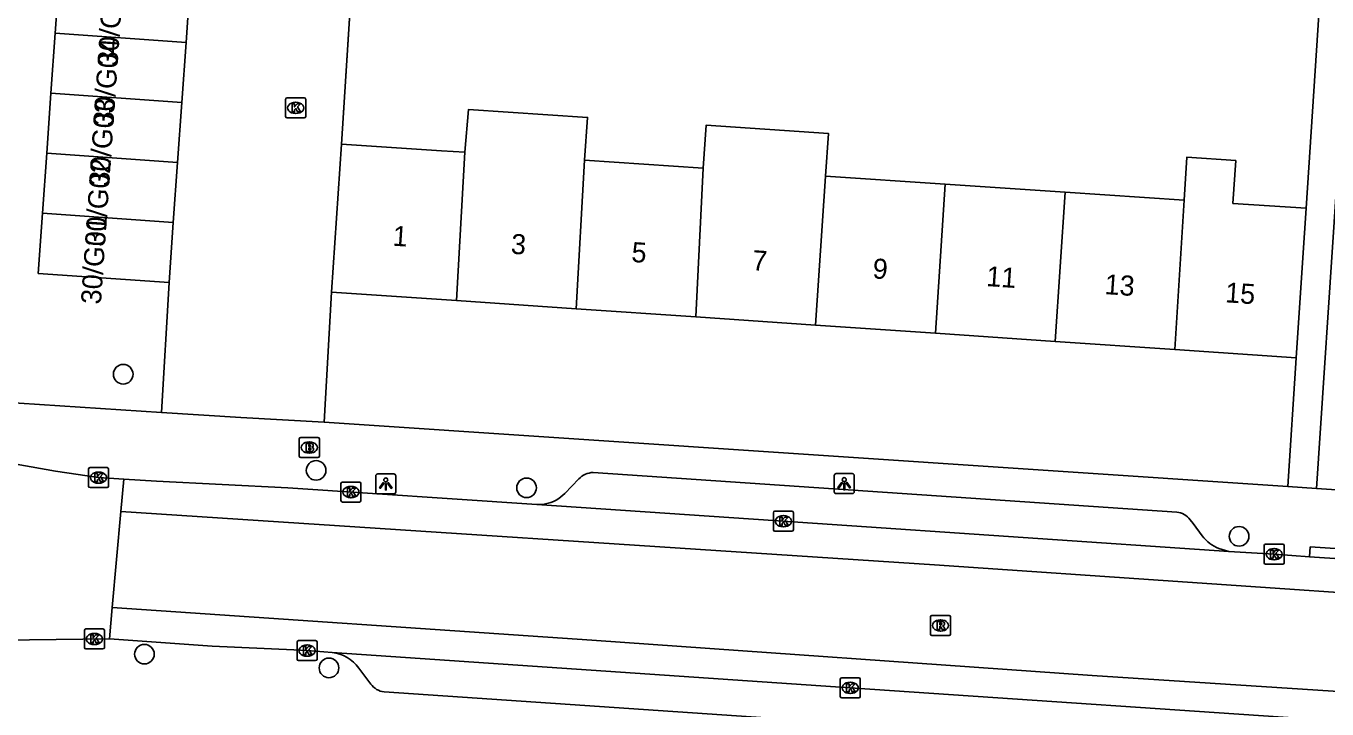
# Model space of a CAD drawing. Extents: x 161848 to 162726, y 385382 to 386521.
# Drawn here: x 162036.5 to 162101.4, y 385740.7 to 385774.8 of the extents above; entities that cross this region are included whole.
import ezdxf

# ---------------------------------------------------------------- set-up
doc = ezdxf.new("R2010")
doc.units = 0
for name, color, linetype in [('IMGEO_Boom', 7, 'Continuous'), ('IMGEO_Brandkraan', 7, 'Continuous'), ('IMGEO_Kolk', 7, 'Continuous'), ('IMGEO_Lichtpunt', 7, 'Continuous'), ('IMGEO_Muur', 7, 'Continuous'), ('IMGEO_Pand', 7, 'Continuous'), ('IMGEO_Pand_nummerreeks', 7, 'Continuous'), ('IMGEO_Rijbaan_lokaal_gesloten', 7, 'Continuous'), ('IMGEO_Rijbaan_lokaal_open', 7, 'Continuous'), ('IMGEO_Rioolput', 7, 'Continuous'), ('IMGEO_Voetpad_open', 7, 'Continuous')]:
    doc.layers.add(name, color=color, linetype=linetype)

msp = doc.modelspace()

# ---------------------------------------------------------------- linework, layer by layer
at = {"layer": 'IMGEO_Boom'}
for centre in [(162041.355, 385757.451), (162050.975, 385752.654), (162061.466, 385751.784), (162096.994, 385749.363), (162042.412, 385743.486), (162051.615, 385742.801)]:
    msp.add_circle(centre, 0.489, dxfattribs=at)
at = {"layer": 'IMGEO_Brandkraan'}
for p, q in [((162050.134, 385753.369), (162050.134, 385754.221)), ((162050.209, 385754.295), (162051.061, 385754.295)), ((162051.135, 385754.221), (162051.135, 385753.369)), ((162050.645, 385753.515), (162050.62, 385753.515)), ((162050.622, 385754.075), (162050.647, 385754.075)), ((162051.061, 385753.295), (162050.209, 385753.295))]:
    msp.add_line(p, q, dxfattribs=at)
for points in [[(162050.134, 385753.369), (162050.134, 385754.221)], [(162050.209, 385754.295), (162051.061, 385754.295)], [(162051.135, 385754.221), (162051.135, 385753.369)], [(162050.482, 385753.995), (162050.482, 385753.595), (162050.695, 385753.595)], [(162050.713, 385753.995), (162050.482, 385753.995)], [(162050.661, 385753.914), (162050.607, 385753.914), (162050.607, 385753.838)], [(162050.607, 385753.838), (162050.66, 385753.838)], [(162050.669, 385753.762), (162050.607, 385753.762), (162050.607, 385753.681)], [(162050.607, 385753.681), (162050.669, 385753.681)], [(162051.061, 385753.295), (162050.209, 385753.295)]]:
    msp.add_lwpolyline(points, dxfattribs=at)
for centre, radius, start, end in [((162050.211, 385754.219), 0.0765, 91.55205, 178.44795), ((162050.211, 385754.219), 0.0765, 91.55205, 178.44795), ((162051.059, 385754.219), 0.0765, 1.55205, 88.44795), ((162051.059, 385754.219), 0.0765, 1.55205, 88.44795), ((162050.662, 385753.876), 0.0379, 267.82845, 90.93552), ((162050.67, 385753.721), 0.0404, 269.87594, 90.50774), ((162050.701, 385753.846), 0.251, 268.66757, 293.53466), ((162050.717, 385753.85), 0.145, 59.4692, 91.53667), ((162050.742, 385753.897), 0.0922, 285.51372, 58.15012), ((162050.747, 385753.705), 0.105, 301.31148, 78.98903), ((162050.211, 385753.371), 0.0765, 181.55205, 268.44795), ((162050.211, 385753.371), 0.0765, 181.55205, 268.44795), ((162051.059, 385753.371), 0.0765, 271.55205, 358.44795), ((162051.059, 385753.371), 0.0765, 271.55205, 358.44795)]:
    msp.add_arc(centre, radius, start, end, dxfattribs=at)
for centre, major_axis, ratio, start_param, end_param in [((162050.621, 385753.795), (-0.387, 0.002), 0.722429, 4.712389, 7.853982), ((162050.646, 385753.795), (-0.39, 0.002), 0.717154, 1.570796, 4.712389)]:
    msp.add_ellipse(centre, major_axis=major_axis, ratio=ratio, start_param=start_param, end_param=end_param, dxfattribs=at)
at = {"layer": 'IMGEO_Kolk'}
for p, q in [((162049.455, 385770.312), (162049.455, 385771.164)), ((162049.53, 385771.238), (162050.382, 385771.238)), ((162049.943, 385771.018), (162049.968, 385771.018)), ((162050.456, 385771.164), (162050.456, 385770.312)), ((162049.966, 385770.458), (162049.941, 385770.458)), ((162050.382, 385770.238), (162049.53, 385770.238)), ((162039.625, 385751.867), (162039.625, 385752.719)), ((162039.7, 385752.793), (162040.552, 385752.793)), ((162040.113, 385752.573), (162040.138, 385752.573)), ((162040.626, 385752.719), (162040.626, 385751.867)), ((162040.552, 385751.793), (162039.7, 385751.793)), ((162040.136, 385752.013), (162040.111, 385752.013)), ((162052.21, 385751.147), (162052.21, 385751.999)), ((162052.285, 385752.073), (162053.137, 385752.073)), ((162052.698, 385751.853), (162052.723, 385751.853)), ((162053.211, 385751.999), (162053.211, 385751.147)), ((162053.137, 385751.073), (162052.285, 385751.073)), ((162052.721, 385751.293), (162052.696, 385751.293)), ((162073.772, 385749.691), (162073.772, 385750.543)), ((162073.847, 385750.617), (162074.699, 385750.617)), ((162074.26, 385750.397), (162074.285, 385750.397)), ((162074.773, 385750.543), (162074.773, 385749.691)), ((162074.699, 385749.617), (162073.847, 385749.617)), ((162074.283, 385749.837), (162074.258, 385749.837)), ((162098.316, 385748.974), (162099.168, 385748.974)), ((162098.241, 385748.048), (162098.241, 385748.9)), ((162098.729, 385748.754), (162098.754, 385748.754)), ((162099.242, 385748.9), (162099.242, 385748.048)), ((162099.168, 385747.974), (162098.316, 385747.974)), ((162098.752, 385748.194), (162098.727, 385748.194)), ((162039.419, 385743.818), (162039.419, 385744.67)), ((162039.494, 385744.744), (162040.346, 385744.744)), ((162039.907, 385744.524), (162039.932, 385744.524)), ((162040.42, 385744.67), (162040.42, 385743.818)), ((162040.346, 385743.744), (162039.494, 385743.744)), ((162039.93, 385743.964), (162039.905, 385743.964)), ((162050.023, 385743.237), (162050.023, 385744.089)), ((162050.098, 385744.163), (162050.95, 385744.163)), ((162050.511, 385743.943), (162050.536, 385743.943)), ((162051.024, 385744.089), (162051.024, 385743.237)), ((162050.95, 385743.163), (162050.098, 385743.163)), ((162050.534, 385743.383), (162050.509, 385743.383)), ((162077.106, 385741.379), (162077.106, 385742.231)), ((162077.181, 385742.305), (162078.033, 385742.305)), ((162077.594, 385742.085), (162077.619, 385742.085)), ((162078.107, 385742.231), (162078.107, 385741.379)), ((162078.033, 385741.305), (162077.181, 385741.305)), ((162077.617, 385741.525), (162077.592, 385741.525))]:
    msp.add_line(p, q, dxfattribs=at)
for points in [[(162049.455, 385770.312), (162049.455, 385771.164)], [(162049.53, 385771.238), (162050.382, 385771.238)], [(162050.456, 385771.164), (162050.456, 385770.312)], [(162049.776, 385770.938), (162049.899, 385770.938), (162049.899, 385770.787), (162050.029, 385770.938), (162050.193, 385770.938), (162050.047, 385770.787), (162050.2, 385770.538), (162050.048, 385770.538), (162049.963, 385770.702), (162049.899, 385770.635), (162049.899, 385770.538), (162049.776, 385770.538), (162049.776, 385770.938)], [(162050.382, 385770.238), (162049.53, 385770.238)], [(162039.625, 385751.867), (162039.625, 385752.719)], [(162039.7, 385752.793), (162040.552, 385752.793)], [(162039.946, 385752.493), (162040.069, 385752.493), (162040.069, 385752.342), (162040.199, 385752.493), (162040.363, 385752.493), (162040.217, 385752.342), (162040.37, 385752.093), (162040.218, 385752.093), (162040.133, 385752.257), (162040.069, 385752.19), (162040.069, 385752.093), (162039.946, 385752.093), (162039.946, 385752.493)], [(162040.626, 385752.719), (162040.626, 385751.867)], [(162040.552, 385751.793), (162039.7, 385751.793)], [(162052.21, 385751.147), (162052.21, 385751.999)], [(162052.285, 385752.073), (162053.137, 385752.073)], [(162052.531, 385751.773), (162052.654, 385751.773), (162052.654, 385751.622), (162052.784, 385751.773), (162052.948, 385751.773), (162052.802, 385751.622), (162052.955, 385751.373), (162052.803, 385751.373), (162052.718, 385751.537), (162052.654, 385751.47), (162052.654, 385751.373), (162052.531, 385751.373), (162052.531, 385751.773)], [(162053.211, 385751.999), (162053.211, 385751.147)], [(162053.137, 385751.073), (162052.285, 385751.073)], [(162073.772, 385749.691), (162073.772, 385750.543)], [(162073.847, 385750.617), (162074.699, 385750.617)], [(162074.093, 385750.317), (162074.216, 385750.317), (162074.216, 385750.166), (162074.346, 385750.317), (162074.51, 385750.317), (162074.364, 385750.166), (162074.517, 385749.917), (162074.365, 385749.917), (162074.28, 385750.081), (162074.216, 385750.014), (162074.216, 385749.917), (162074.093, 385749.917), (162074.093, 385750.317)], [(162074.773, 385750.543), (162074.773, 385749.691)], [(162074.699, 385749.617), (162073.847, 385749.617)], [(162098.316, 385748.974), (162099.168, 385748.974)], [(162098.241, 385748.048), (162098.241, 385748.9)], [(162098.562, 385748.674), (162098.685, 385748.674), (162098.685, 385748.523), (162098.815, 385748.674), (162098.979, 385748.674), (162098.833, 385748.523), (162098.986, 385748.274), (162098.834, 385748.274), (162098.749, 385748.438), (162098.685, 385748.371), (162098.685, 385748.274), (162098.562, 385748.274), (162098.562, 385748.674)], [(162099.242, 385748.9), (162099.242, 385748.048)], [(162099.168, 385747.974), (162098.316, 385747.974)], [(162039.419, 385743.818), (162039.419, 385744.67)], [(162039.494, 385744.744), (162040.346, 385744.744)], [(162039.74, 385744.444), (162039.863, 385744.444), (162039.863, 385744.293), (162039.993, 385744.444), (162040.157, 385744.444), (162040.011, 385744.293), (162040.164, 385744.044), (162040.012, 385744.044), (162039.927, 385744.208), (162039.863, 385744.141), (162039.863, 385744.044), (162039.74, 385744.044), (162039.74, 385744.444)], [(162040.42, 385744.67), (162040.42, 385743.818)], [(162040.346, 385743.744), (162039.494, 385743.744)], [(162050.023, 385743.237), (162050.023, 385744.089)], [(162050.098, 385744.163), (162050.95, 385744.163)], [(162050.344, 385743.863), (162050.467, 385743.863), (162050.467, 385743.712), (162050.597, 385743.863), (162050.761, 385743.863), (162050.615, 385743.712), (162050.768, 385743.463), (162050.616, 385743.463), (162050.531, 385743.627), (162050.467, 385743.56), (162050.467, 385743.463), (162050.344, 385743.463), (162050.344, 385743.863)], [(162051.024, 385744.089), (162051.024, 385743.237)], [(162050.95, 385743.163), (162050.098, 385743.163)], [(162077.106, 385741.379), (162077.106, 385742.231)], [(162077.181, 385742.305), (162078.033, 385742.305)], [(162077.427, 385742.005), (162077.55, 385742.005), (162077.55, 385741.854), (162077.68, 385742.005), (162077.844, 385742.005), (162077.698, 385741.854), (162077.851, 385741.605), (162077.699, 385741.605), (162077.614, 385741.769), (162077.55, 385741.702), (162077.55, 385741.605), (162077.427, 385741.605), (162077.427, 385742.005)], [(162078.107, 385742.231), (162078.107, 385741.379)], [(162078.033, 385741.305), (162077.181, 385741.305)]]:
    msp.add_lwpolyline(points, dxfattribs=at)
for centre, start, end in [((162049.532, 385771.162), 91.55205, 178.44795), ((162049.532, 385771.162), 91.55205, 178.44795), ((162050.38, 385771.162), 1.55205, 88.44795), ((162050.38, 385771.162), 1.55205, 88.44795), ((162049.532, 385770.314), 181.55205, 268.44795), ((162049.532, 385770.314), 181.55205, 268.44795), ((162050.38, 385770.314), 271.55205, 358.44795), ((162050.38, 385770.314), 271.55205, 358.44795), ((162039.702, 385752.717), 91.55205, 178.44795), ((162039.702, 385752.717), 91.55205, 178.44795), ((162040.55, 385752.717), 1.55205, 88.44795), ((162040.55, 385752.717), 1.55205, 88.44795), ((162039.702, 385751.869), 181.55205, 268.44795), ((162039.702, 385751.869), 181.55205, 268.44795), ((162040.55, 385751.869), 271.55205, 358.44795), ((162040.55, 385751.869), 271.55205, 358.44795), ((162052.287, 385751.997), 91.55205, 178.44795), ((162052.287, 385751.997), 91.55205, 178.44795), ((162053.135, 385751.997), 1.55205, 88.44795), ((162053.135, 385751.997), 1.55205, 88.44795), ((162052.287, 385751.149), 181.55205, 268.44795), ((162052.287, 385751.149), 181.55205, 268.44795), ((162053.135, 385751.149), 271.55205, 358.44795), ((162053.135, 385751.149), 271.55205, 358.44795), ((162073.849, 385750.541), 91.55205, 178.44795), ((162073.849, 385750.541), 91.55205, 178.44795), ((162074.697, 385750.541), 1.55205, 88.44795), ((162074.697, 385750.541), 1.55205, 88.44795), ((162073.849, 385749.693), 181.55205, 268.44795), ((162073.849, 385749.693), 181.55205, 268.44795), ((162074.697, 385749.693), 271.55205, 358.44795), ((162074.697, 385749.693), 271.55205, 358.44795), ((162098.318, 385748.898), 91.55205, 178.44795), ((162098.318, 385748.898), 91.55205, 178.44795), ((162099.166, 385748.898), 1.55205, 88.44795), ((162099.166, 385748.898), 1.55205, 88.44795), ((162098.318, 385748.05), 181.55205, 268.44795), ((162098.318, 385748.05), 181.55205, 268.44795), ((162099.166, 385748.05), 271.55205, 358.44795), ((162099.166, 385748.05), 271.55205, 358.44795), ((162039.496, 385744.668), 91.55205, 178.44795), ((162039.496, 385744.668), 91.55205, 178.44795), ((162040.344, 385744.668), 1.55205, 88.44795), ((162040.344, 385744.668), 1.55205, 88.44795), ((162039.496, 385743.82), 181.55205, 268.44795), ((162039.496, 385743.82), 181.55205, 268.44795), ((162040.344, 385743.82), 271.55205, 358.44795), ((162040.344, 385743.82), 271.55205, 358.44795), ((162050.1, 385744.087), 91.55205, 178.44795), ((162050.1, 385744.087), 91.55205, 178.44795), ((162050.948, 385744.087), 1.55205, 88.44795), ((162050.948, 385744.087), 1.55205, 88.44795), ((162050.1, 385743.239), 181.55205, 268.44795), ((162050.1, 385743.239), 181.55205, 268.44795), ((162050.948, 385743.239), 271.55205, 358.44795), ((162050.948, 385743.239), 271.55205, 358.44795), ((162077.183, 385742.229), 91.55205, 178.44795), ((162077.183, 385742.229), 91.55205, 178.44795), ((162078.031, 385742.229), 1.55205, 88.44795), ((162078.031, 385742.229), 1.55205, 88.44795), ((162077.183, 385741.381), 181.55205, 268.44795), ((162077.183, 385741.381), 181.55205, 268.44795), ((162078.031, 385741.381), 271.55205, 358.44795), ((162078.031, 385741.381), 271.55205, 358.44795)]:
    msp.add_arc(centre, 0.0765, start, end, dxfattribs=at)
for centre, major_axis, ratio, start_param, end_param in [((162049.942, 385770.738), (-0.387, 0.002), 0.722429, 4.712389, 7.853982), ((162049.967, 385770.738), (-0.39, 0.002), 0.717154, 1.570796, 4.712389), ((162040.112, 385752.293), (-0.387, 0.002), 0.722429, 4.712389, 7.853982), ((162040.137, 385752.293), (-0.39, 0.002), 0.717154, 1.570796, 4.712389), ((162052.697, 385751.573), (-0.387, 0.002), 0.722429, 4.712389, 7.853982), ((162052.722, 385751.573), (-0.39, 0.002), 0.717154, 1.570796, 4.712389), ((162074.259, 385750.117), (-0.387, 0.002), 0.722429, 4.712389, 7.853982), ((162074.284, 385750.117), (-0.39, 0.002), 0.717154, 1.570796, 4.712389), ((162098.728, 385748.474), (-0.387, 0.002), 0.722429, 4.712389, 7.853982), ((162098.753, 385748.474), (-0.39, 0.002), 0.717154, 1.570796, 4.712389), ((162039.906, 385744.244), (-0.387, 0.002), 0.722429, 4.712389, 7.853982), ((162039.931, 385744.244), (-0.39, 0.002), 0.717154, 1.570796, 4.712389), ((162050.51, 385743.663), (-0.387, 0.002), 0.722429, 4.712389, 7.853982), ((162050.535, 385743.663), (-0.39, 0.002), 0.717154, 1.570796, 4.712389), ((162077.593, 385741.805), (-0.387, 0.002), 0.722429, 4.712389, 7.853982), ((162077.618, 385741.805), (-0.39, 0.002), 0.717154, 1.570796, 4.712389)]:
    msp.add_ellipse(centre, major_axis=major_axis, ratio=ratio, start_param=start_param, end_param=end_param, dxfattribs=at)
at = {"layer": 'IMGEO_Lichtpunt'}
for p, q in [((162053.95, 385752.383), (162053.95, 385751.576)), ((162053.95, 385752.383), (162053.95, 385751.576)), ((162054.852, 385752.478), (162054.044, 385752.478)), ((162054.852, 385752.478), (162054.044, 385752.478)), ((162054.946, 385751.576), (162054.946, 385752.383)), ((162054.946, 385751.576), (162054.946, 385752.383)), ((162076.806, 385752.396), (162076.806, 385751.589)), ((162076.806, 385752.396), (162076.806, 385751.589)), ((162077.708, 385752.491), (162076.9, 385752.491)), ((162077.708, 385752.491), (162076.9, 385752.491)), ((162077.802, 385751.589), (162077.802, 385752.396)), ((162077.802, 385751.589), (162077.802, 385752.396)), ((162054.044, 385751.482), (162054.852, 385751.482)), ((162054.044, 385751.482), (162054.852, 385751.482)), ((162076.9, 385751.495), (162077.708, 385751.495)), ((162076.9, 385751.495), (162077.708, 385751.495))]:
    msp.add_line(p, q, dxfattribs=at)
for points in [[(162054.324, 385752.047), (162054.363, 385752.019), (162054.175, 385751.757), (162054.137, 385751.784), (162054.324, 385752.047)], [(162054.426, 385751.999), (162054.473, 385751.999), (162054.473, 385751.677), (162054.426, 385751.677), (162054.426, 385751.999)], [(162054.536, 385752.019), (162054.574, 385752.046), (162054.761, 385751.784), (162054.722, 385751.756), (162054.536, 385752.019)], [(162077.18, 385752.06), (162077.219, 385752.032), (162077.031, 385751.77), (162076.993, 385751.797), (162077.18, 385752.06)], [(162077.282, 385752.012), (162077.329, 385752.012), (162077.329, 385751.69), (162077.282, 385751.69), (162077.282, 385752.012)], [(162077.392, 385752.032), (162077.43, 385752.059), (162077.617, 385751.797), (162077.578, 385751.769), (162077.392, 385752.032)]]:
    msp.add_lwpolyline(points, dxfattribs=at)
for centre in [(162054.449, 385752.181), (162077.305, 385752.194)]:
    msp.add_circle(centre, 0.0994, dxfattribs=at)
for centre, start, end in [((162054.044, 385752.383), 90, 180), ((162054.044, 385752.383), 90, 180), ((162054.852, 385752.383), 0, 90), ((162054.852, 385752.383), 0, 90), ((162076.9, 385752.396), 90, 180), ((162076.9, 385752.396), 90, 180), ((162077.708, 385752.396), 0, 90), ((162077.708, 385752.396), 0, 90), ((162054.044, 385751.576), 180, 270), ((162054.044, 385751.576), 180, 270), ((162054.852, 385751.576), 270, 0), ((162054.852, 385751.576), 270, 360), ((162076.9, 385751.589), 180, 270), ((162076.9, 385751.589), 180, 270), ((162077.708, 385751.589), 270, 0), ((162077.708, 385751.589), 270, 360)]:
    msp.add_arc(centre, 0.0946, start, end, dxfattribs=at)
at = {"layer": 'IMGEO_Muur'}
msp.add_lwpolyline([(162052.981, 385780.697), (162052.24, 385768.934)], dxfattribs=at)
at = {"layer": 'IMGEO_Pand'}
for points in [[(162038.176, 385777.463), (162037.964, 385774.467)], [(162044.487, 385774.006), (162044.699, 385777.002)], [(162037.964, 385774.467), (162037.752, 385771.472)], [(162044.487, 385774.006), (162037.964, 385774.467)], [(162044.275, 385771.011), (162044.487, 385774.006)], [(162037.752, 385771.472), (162037.541, 385768.476)], [(162037.752, 385771.472), (162044.275, 385771.011)], [(162044.064, 385768.015), (162044.275, 385771.011)], [(162058.397, 385768.524), (162058.565, 385770.658), (162064.512, 385770.262), (162064.353, 385768.128)], [(162070.273, 385767.734), (162070.414, 385769.87), (162076.517, 385769.464), (162076.375, 385767.328)], [(162037.329, 385765.48), (162037.541, 385768.476)], [(162037.541, 385768.476), (162044.064, 385768.015)], [(162052.24, 385768.934), (162051.749, 385761.546)], [(162052.24, 385768.934), (162057.229, 385768.602), (162058.397, 385768.524)], [(162057.97, 385761.123), (162058.397, 385768.524)], [(162044.064, 385768.015), (162043.852, 385765.019)], [(162063.94, 385760.716), (162064.353, 385768.128)], [(162064.353, 385768.128), (162070.273, 385767.734)], [(162070.273, 385767.734), (162069.91, 385760.31)], [(162094.251, 385766.139), (162094.387, 385768.275), (162096.827, 385768.113), (162096.685, 385765.977), (162100.343, 385765.734)], [(162075.881, 385759.904), (162076.375, 385767.328)], [(162076.375, 385767.328), (162082.346, 385766.931)], [(162081.851, 385759.498), (162082.346, 385766.931)], [(162082.346, 385766.931), (162088.317, 385766.534)], [(162088.317, 385766.534), (162087.821, 385759.091)], [(162088.317, 385766.534), (162094.251, 385766.139)], [(162093.792, 385758.685), (162094.251, 385766.139)], [(162043.64, 385762.023), (162037.117, 385762.484), (162037.329, 385765.48)], [(162043.852, 385765.019), (162037.329, 385765.48)], [(162100.343, 385765.734), (162100.179, 385763.262), (162099.847, 385758.273)], [(162043.852, 385765.019), (162043.64, 385762.023)], [(162057.97, 385761.123), (162051.749, 385761.546)], [(162063.94, 385760.716), (162057.97, 385761.123)], [(162069.91, 385760.31), (162063.94, 385760.716)], [(162075.881, 385759.904), (162069.91, 385760.31)], [(162081.851, 385759.498), (162075.881, 385759.904)], [(162087.821, 385759.091), (162081.851, 385759.498)], [(162093.792, 385758.685), (162087.821, 385759.091)], [(162099.847, 385758.273), (162093.792, 385758.685)]]:
    msp.add_lwpolyline(points, dxfattribs=at)
at = {"layer": 'IMGEO_Rijbaan_lokaal_gesloten'}
for points in [[(162041.383, 385752.223), (162041.237, 385750.595)], [(162061.976, 385750.946), (162049.571, 385751.785), (162043.017, 385752.11), (162041.383, 385752.223)], [(162096.489, 385748.608), (162075.978, 385750), (162061.976, 385750.946)], [(162041.237, 385750.595), (162040.807, 385745.812)], [(162041.237, 385750.595), (162081.802, 385747.948), (162119.648, 385745.356), (162154.961, 385742.34), (162177.493, 385740.169), (162184.046, 385739.537), (162186.362, 385739.314)], [(162100.507, 385748.337), (162098.738, 385748.473), (162096.489, 385748.608)], [(162104.27, 385748.089), (162100.507, 385748.337)], [(162040.807, 385745.812), (162040.667, 385744.254)], [(162186.826, 385734.287), (162184.65, 385734.497), (162177.9, 385735.148), (162157.058, 385737.16), (162131.864, 385739.672), (162089.667, 385742.424), (162064.724, 385744.182), (162040.807, 385745.812)], [(162040.667, 385744.254), (162045.788, 385743.892), (162049.86, 385743.699), (162050.52, 385743.664), (162051.772, 385743.57)], [(162051.772, 385743.57), (162077.603, 385741.806), (162103.122, 385740.074), (162116.37, 385739.177)]]:
    msp.add_lwpolyline(points, dxfattribs=at)
at = {"layer": 'IMGEO_Rijbaan_lokaal_open'}
for points in [[(162052.981, 385780.69), (162052.24, 385768.934)], [(162043.64, 385762.023), (162043.266, 385755.546)], [(162051.749, 385761.546), (162051.378, 385755.062)], [(162051.378, 385755.062), (162047.226, 385755.289), (162043.266, 385755.546)], [(162041.383, 385752.223), (162040.126, 385752.293), (162037.987, 385752.616), (162032.83, 385753.535)], [(162028.674, 385744.095), (162040.667, 385744.254)]]:
    msp.add_lwpolyline(points, dxfattribs=at)
at = {"layer": 'IMGEO_Rioolput'}
for p, q in [((162081.607, 385744.49), (162081.607, 385745.342)), ((162081.682, 385745.416), (162082.534, 385745.416)), ((162082.095, 385745.196), (162082.12, 385745.196)), ((162082.608, 385745.342), (162082.608, 385744.49)), ((162082.534, 385744.416), (162081.682, 385744.416)), ((162082.118, 385744.636), (162082.093, 385744.636))]:
    msp.add_line(p, q, dxfattribs=at)
for points in [[(162081.607, 385744.49), (162081.607, 385745.342)], [(162081.682, 385745.416), (162082.534, 385745.416)], [(162082.196, 385745.114), (162081.944, 385745.116), (162081.944, 385744.716)], [(162082.122, 385745.035), (162082.068, 385745.035), (162082.068, 385744.954)], [(162082.608, 385745.342), (162082.608, 385744.49)], [(162082.534, 385744.416), (162081.682, 385744.416)], [(162081.944, 385744.716), (162082.068, 385744.716), (162082.068, 385744.878), (162082.079, 385744.878)], [(162082.068, 385744.954), (162082.12, 385744.954)], [(162082.126, 385744.849), (162082.197, 385744.716), (162082.337, 385744.716), (162082.272, 385744.842)]]:
    msp.add_lwpolyline(points, dxfattribs=at)
for centre, radius, start, end in [((162081.684, 385745.34), 0.0765, 91.55205, 178.44795), ((162081.684, 385745.34), 0.0765, 91.55205, 178.44795), ((162082.128, 385744.939), 0.0964, 77.00612, 93.18647), ((162082.142, 385744.996), 0.0378, 276.66336, 79.67722), ((162082.195, 385745.004), 0.109, 350.36119, 89.41601), ((162082.532, 385745.34), 0.0765, 1.55205, 88.44795), ((162082.532, 385745.34), 0.0765, 1.55205, 88.44795), ((162081.684, 385744.492), 0.0765, 181.55205, 268.44795), ((162081.684, 385744.492), 0.0765, 181.55205, 268.44795), ((162082.078, 385744.825), 0.0533, 26.02933, 88.69889), ((162082.104, 385745.143), 0.19, 274.7715, 282.96867), ((162082.193, 385745.004), 0.112, 277.58423, 350.98172), ((162082.177, 385744.789), 0.108, 29.51342, 73.79051), ((162082.532, 385744.492), 0.0765, 271.55205, 358.44795), ((162082.532, 385744.492), 0.0765, 271.55205, 358.44795)]:
    msp.add_arc(centre, radius, start, end, dxfattribs=at)
for centre, major_axis, ratio, start_param, end_param in [((162082.094, 385744.916), (-0.387, 0.002), 0.722429, 4.712389, 7.853982), ((162082.119, 385744.916), (-0.39, 0.002), 0.717154, 1.570796, 4.712389)]:
    msp.add_ellipse(centre, major_axis=major_axis, ratio=ratio, start_param=start_param, end_param=end_param, dxfattribs=at)
at = {"layer": 'IMGEO_Voetpad_open'}
for points in [[(162100.343, 385765.734), (162101.098, 385777.434), (162099.933, 385777.509)], [(162101.833, 385766.551), (162100.851, 385751.751)], [(162099.417, 385751.847), (162099.847, 385758.273)], [(162043.266, 385755.546), (162035.139, 385756.073)], [(162051.378, 385755.062), (162099.417, 385751.847)], [(162063.071, 385751.25), (162063.38, 385751.509), (162064.079, 385752.231)], [(162064.78, 385752.549), (162093.885, 385750.572)], [(162099.417, 385751.847), (162100.851, 385751.751)], [(162100.851, 385751.751), (162123.16, 385750.258)], [(162094.556, 385750.191), (162094.699, 385750), (162095.159, 385749.384)], [(162095.982, 385748.75), (162096.489, 385748.608)], [(162100.507, 385748.337), (162100.54, 385748.835), (162104.302, 385748.587), (162104.27, 385748.089)], [(162053.704, 385741.994), (162053.099, 385742.794)], [(162100.969, 385738.434), (162054.362, 385741.601)]]:
    msp.add_lwpolyline(points, dxfattribs=at)
for centre, radius, start, end in [((162064.812, 385751.546), 1.003, 91.84252, 136.95915), ((162062.058, 385752.775), 1.831, 267.43968, 303.59234), ((162093.786, 385749.616), 0.961, 36.75191, 84.07147), ((162096.784, 385750.643), 2.056, 217.75633, 247.02578), ((162051.542, 385741.655), 1.929, 36.19759, 83.16612), ((162054.479, 385742.544), 0.95, 215.37016, 262.9331)]:
    msp.add_arc(centre, radius, start, end, dxfattribs=at)

# ---------------------------------------------------------------- texts
at = {"layer": 'IMGEO_Pand_nummerreeks'}
for s, rotation, p in [('30/G05', 86.02327, (162041.067, 385772.794)), ('30/G04', 86.02327, (162040.859, 385769.797)), ('30/G03', 86.02327, (162040.651, 385766.8)), ('30/G02', 86.02327, (162040.442, 385763.797)), ('30/G01', 86.02327, (162040.242, 385760.917)), ('1', 356.10711, (162054.765, 385763.867)), ('3', 356.10711, (162060.663, 385763.466)), ('5', 356.10711, (162066.676, 385763.056)), ('7', 356.10711, (162072.688, 385762.647)), ('9', 356.10711, (162078.7, 385762.238)), ('11', 356.10711, (162084.368, 385761.852)), ('13', 356.10711, (162090.267, 385761.451)), ('15', 356.10711, (162096.279, 385761.042))]:
    msp.add_text(s, height=1, rotation=rotation, dxfattribs=at).set_placement(p)

doc.saveas('drawing.dxf')
